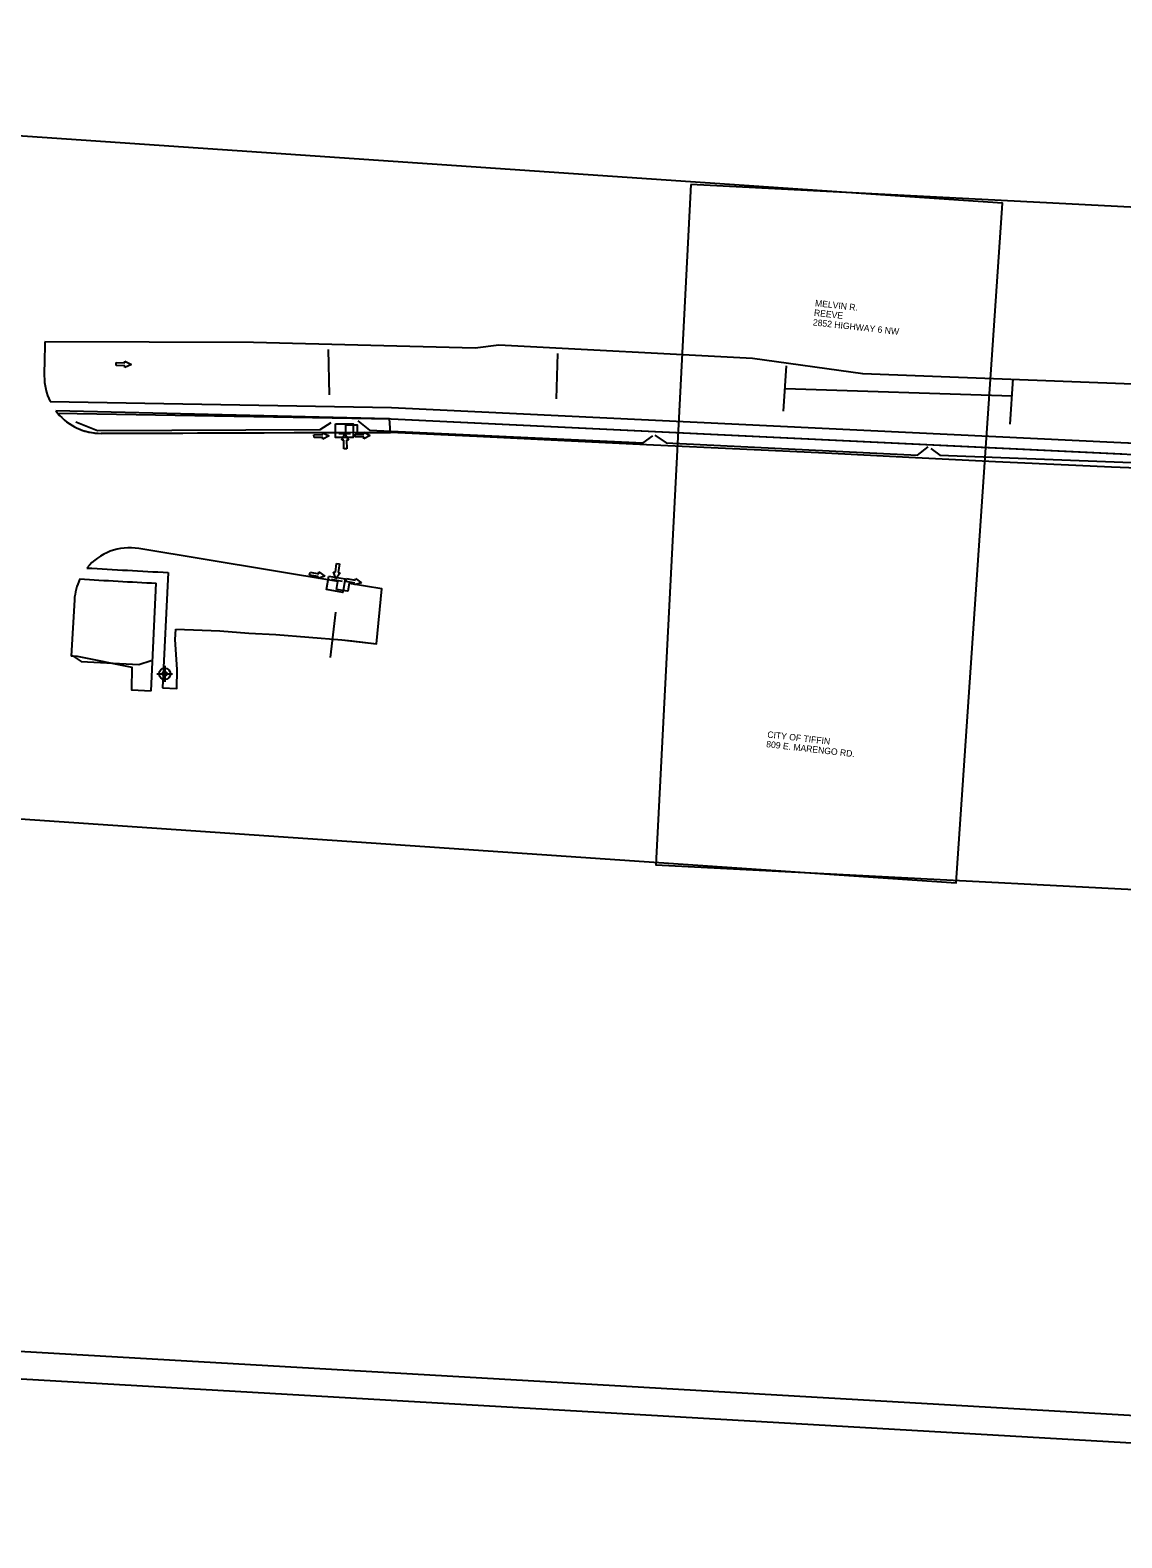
# Model space of a CAD drawing. Extents: x 20499990 to 20505779, y 7953198 to 7954399.
# Drawn here: x 20504549 to 20505029, y 7953198 to 7953862 of the extents above; entities that cross this region are included whole.
import ezdxf

# ---------------------------------------------------------------- set-up
doc = ezdxf.new("R2010")
doc.units = 0
for name, color, linetype in [('Building', 7, 'Continuous'), ('ClearGrub', 7, 'Continuous'), ('Draft_DNC', 7, 'Continuous'), ('dsnCellElements', 7, 'Continuous'), ('ErosionControl', 7, 'Continuous'), ('NamedBoundary', 7, 'Continuous'), ('Seeding', 7, 'Continuous'), ('Text', 7, 'Continuous')]:
    doc.layers.add(name, color=color, linetype=linetype)

msp = doc.modelspace()

# ---------------------------------------------------------------- linework, layer by layer
at = {"layer": 'Building'}
for p, q in [((20504555.07, 7953724.24), (20504554.94, 7953714.54)), ((20504554.97, 7953717.03), (20504554.87, 7953709.32)), ((20504557.42, 7953697.98), (20504707.7, 7953695.4)), ((20504560.72, 7953692.92), (20504707.68, 7953690.4)), ((20504707.7, 7953695.4), (20505028.88, 7953679.93)), ((20504707.68, 7953690.4), (20505029.34, 7953674.9)), ((20504707.3, 7953684.41), (20504579.95, 7953683.99)), ((20504684.17, 7953618.69), (20504596.48, 7953633.27)), ((20504609.4, 7953622.72), (20504606.93, 7953571.99)), ((20504601.86, 7953570.55), (20504604.16, 7953617.99)), ((20504683.59, 7953615.27), (20504684.17, 7953618.69)), ((20504568.15, 7953610.62), (20504566.72, 7953585.85)), ((20504612.77, 7953597.78), (20504632.15, 7953597.07))]:
    msp.add_line(p, q, dxfattribs=at)
for points in [[(20505264.52, 7953761.4), (20505255.15, 7953760.64), (20505223.48, 7953728.42), (20505118.14, 7953708.13), (20505064.87, 7953704.49), (20504915.31, 7953710.24), (20504866.73, 7953716.98), (20504755.09, 7953722.82), (20504744.66, 7953721.51), (20504646.98, 7953723.97), (20504555.07, 7953724.24)], [(20505061.3, 7953667.91), (20505051.67, 7953668.07), (20505024.81, 7953669.14), (20505009.01, 7953669.85), (20504973.68, 7953671.52), (20504935.49, 7953673.34), (20504898.88, 7953675.21), (20504861.14, 7953676.98), (20504823.16, 7953678.8), (20504783.91, 7953680.73), (20504745.3, 7953682.65), (20504710.5, 7953684.26), (20504707.21, 7953684.41)], [(20504632.15, 7953597.07), (20504644.99, 7953596.03), (20504656.88, 7953595.36), (20504685.89, 7953593.08), (20504690.26, 7953592.59), (20504701.1, 7953591.37), (20504703.49, 7953615.5), (20504689.1, 7953617.88), (20504688.52, 7953614.44), (20504686.25, 7953614.8), (20504683.59, 7953615.27)], [(20504606.93, 7953571.99), (20504613.28, 7953571.63), (20504613.37, 7953579.96), (20504612.45, 7953593.14), (20504612.77, 7953597.78)], [(20504566.73, 7953585.99), (20504569.42, 7953585.84), (20504593.38, 7953581.01), (20504593.28, 7953571), (20504601.86, 7953570.55)]]:
    msp.add_lwpolyline(points, dxfattribs=at)
for centre, radius, start, end in [((20504579.87, 7953708.99), 25, 179.23932, 206.12913), ((20504579.87, 7953708.99), 25, 219.99809, 270.18967), ((20505067.33, 7954478), 799, 267.24196, 281.40324), ((20504592.48, 7953609.23), 24.37, 80.56251, 140.65245), ((20504592.48, 7953609.23), 24.37, 154.15745, 176.71189), ((20504906, 7959377.59), 5767.5, 266.665603, 267.000099), ((20504906, 7959377.59), 5762.5, 266.69346, 267.049627)]:
    msp.add_arc(centre, radius, start, end, dxfattribs=at)
at = {"layer": 'ClearGrub'}
for p, q in [((20504607.89, 7953581.59), (20504607.89, 7953574.59)), ((20504604.39, 7953578.09), (20504611.39, 7953578.09))]:
    msp.add_line(p, q, dxfattribs=at)
for radius in [2.5, 1]:
    msp.add_circle((20504607.89, 7953578.09), radius, dxfattribs=at)
at = {"layer": 'Draft_DNC'}
for points in [[(20502378.98, 7953404.37), (20502465.54, 7954399.08), (20505611.36, 7954341.07), (20505615.95, 7953217.82)], [(20502519.96, 7953384.14), (20502606.52, 7954378.84), (20505752.34, 7954320.84), (20505756.93, 7953197.59)]]:
    msp.add_lwpolyline(points, close=True, dxfattribs=at)
at = {"layer": 'dsnCellElements'}
for p, q in [((20504586.53, 7953713.9), (20504586.57, 7953715.17)), ((20504590.35, 7953713.79), (20504586.53, 7953713.9)), ((20504586.57, 7953715.17), (20504590.39, 7953715.06)), ((20504593.23, 7953714.34), (20504590.33, 7953712.99)), ((20504590.33, 7953712.99), (20504590.35, 7953713.79)), ((20504590.39, 7953715.06), (20504590.41, 7953715.85)), ((20504590.41, 7953715.85), (20504593.23, 7953714.34)), ((20504673.63, 7953683.38), (20504677.45, 7953683.48)), ((20504673.67, 7953682.11), (20504673.63, 7953683.38)), ((20504677.48, 7953682.21), (20504673.67, 7953682.11)), ((20504677.43, 7953684.28), (20504680.33, 7953682.93)), ((20504677.45, 7953683.48), (20504677.43, 7953684.28)), ((20504677.5, 7953681.42), (20504677.48, 7953682.21)), ((20504680.33, 7953682.93), (20504677.5, 7953681.42)), ((20504685.92, 7953680.93), (20504687.26, 7953683.83)), ((20504686.71, 7953680.95), (20504685.92, 7953680.93)), ((20504686.82, 7953677.14), (20504686.71, 7953680.95)), ((20504687.26, 7953683.83), (20504688.78, 7953681.02)), ((20504688.78, 7953681.02), (20504687.98, 7953680.99)), ((20504687.98, 7953680.99), (20504688.09, 7953677.18)), ((20504691.74, 7953682.43), (20504691.75, 7953683.7)), ((20504695.55, 7953682.39), (20504691.74, 7953682.43)), ((20504691.75, 7953683.7), (20504695.56, 7953683.67)), ((20504698.42, 7953683), (20504695.54, 7953681.6)), ((20504695.54, 7953681.6), (20504695.55, 7953682.39)), ((20504695.56, 7953683.67), (20504695.57, 7953684.46)), ((20504695.57, 7953684.46), (20504698.42, 7953683)), ((20504688.09, 7953677.18), (20504686.82, 7953677.14)), ((20504683.04, 7953622.86), (20504683.55, 7953626.64)), ((20504683.55, 7953626.64), (20504684.81, 7953626.47)), ((20504684.81, 7953626.47), (20504684.3, 7953622.69)), ((20504671.72, 7953621.55), (20504671.93, 7953622.81)), ((20504675.48, 7953620.9), (20504671.72, 7953621.55)), ((20504671.93, 7953622.81), (20504675.69, 7953622.16)), ((20504678.41, 7953621.04), (20504675.34, 7953620.12)), ((20504675.34, 7953620.12), (20504675.48, 7953620.9)), ((20504675.69, 7953622.16), (20504675.83, 7953622.94)), ((20504675.83, 7953622.94), (20504678.41, 7953621.04)), ((20504683.28, 7953619.94), (20504682.25, 7953622.97)), ((20504682.25, 7953622.97), (20504683.04, 7953622.86)), ((20504685.09, 7953622.58), (20504683.28, 7953619.94)), ((20504684.3, 7953622.69), (20504685.09, 7953622.58)), ((20504687.79, 7953618.76), (20504688.01, 7953620.01)), ((20504688.01, 7953620.01), (20504691.77, 7953619.34)), ((20504691.77, 7953619.34), (20504691.91, 7953620.12)), ((20504691.91, 7953620.12), (20504694.48, 7953618.21)), ((20504691.55, 7953618.08), (20504687.79, 7953618.76)), ((20504694.48, 7953618.21), (20504691.41, 7953617.3)), ((20504691.41, 7953617.3), (20504691.55, 7953618.08))]:
    msp.add_line(p, q, dxfattribs=at)
at = {"layer": 'ErosionControl'}
for p, q in [((20504680.49, 7953700.9), (20504679.98, 7953720.9)), ((20504780.39, 7953699.2), (20504780.96, 7953719.19)), ((20504880.43, 7953693.79), (20504881.72, 7953713.75)), ((20504980.19, 7953688), (20504981.48, 7953707.95)), ((20504881.07, 7953703.77), (20504981.02, 7953700.58)), ((20504706.46, 7953690.42), (20504559.92, 7953693.92)), ((20504579.95, 7953683.99), (20504687.66, 7953684.34)), ((20504689.63, 7953683.77), (20504684.63, 7953683.79)), ((20504692.66, 7953684.36), (20504707.34, 7953684.41)), ((20504681.13, 7953619.76), (20504686.06, 7953618.93)), ((20504680.91, 7953585.31), (20504683.18, 7953605.18))]:
    msp.add_line(p, q, dxfattribs=at)
for points in [[(20504568.79, 7953689.13), (20504578.3, 7953685.24), (20504676.32, 7953685.69), (20504681.24, 7953688.79)], [(20504687.66, 7953684.34), (20504687.67, 7953687.79), (20504692.67, 7953687.77), (20504692.66, 7953684.36)], [(20504692.92, 7953689.57), (20504698.08, 7953685.42), (20504818.62, 7953679.78), (20504822.87, 7953682.91)], [(20504707.34, 7953684.41), (20504706.85, 7953690.4), (20504706.46, 7953690.42)], [(20504823.77, 7953683.14), (20504828.69, 7953679.78), (20504939.39, 7953674.41), (20504944.09, 7953677.99)], [(20504945.21, 7953677.32), (20504949.23, 7953674.41), (20505052.79, 7953670.38), (20505057.71, 7953673.07)], [(20504567.15, 7953586.16), (20504571.11, 7953583.57), (20504596.53, 7953582.2), (20504602, 7953583.95)]]:
    msp.add_lwpolyline(points, dxfattribs=at)
for points in [[(20504683.09, 7953688.24), (20504690.95, 7953688.24), (20504690.95, 7953682.17), (20504683.09, 7953682.17)], [(20504680.11, 7953621.11), (20504687.33, 7953619.9), (20504686.33, 7953613.97), (20504679.11, 7953615.18)]]:
    msp.add_lwpolyline(points, close=True, dxfattribs=at)
msp.add_arc((20504579.87, 7953708.99), 25, 217.05957, 270.18967, dxfattribs=at)
at = {"layer": 'NamedBoundary'}
for points in [[(20504038.63, 7953849.54), (20504018.15, 7953550.24), (20504956.36, 7953486.07), (20504976.83, 7953785.37)], [(20504839.57, 7953793.6), (20504824.13, 7953494), (20505763.38, 7953445.57), (20505778.83, 7953745.18)]]:
    msp.add_lwpolyline(points, close=True, dxfattribs=at)
at = {"layer": 'Seeding'}
for p, q in [((20504555.07, 7953724.24), (20504554.94, 7953714.54)), ((20504554.97, 7953717.03), (20504554.87, 7953709.32)), ((20504557.42, 7953697.98), (20504707.7, 7953695.4)), ((20504560.72, 7953692.92), (20504707.68, 7953690.4)), ((20504707.7, 7953695.4), (20505028.88, 7953679.93)), ((20504707.68, 7953690.4), (20505028.64, 7953674.94)), ((20504707.3, 7953684.41), (20504579.95, 7953683.99)), ((20504684.17, 7953618.69), (20504596.48, 7953633.27)), ((20504609.4, 7953622.72), (20504606.93, 7953571.99)), ((20504601.86, 7953570.55), (20504604.16, 7953617.99)), ((20504683.61, 7953615.28), (20504684.17, 7953618.69)), ((20504568.15, 7953610.62), (20504566.72, 7953585.85)), ((20504612.77, 7953597.78), (20504632.15, 7953597.07))]:
    msp.add_line(p, q, dxfattribs=at)
for points in [[(20505264.52, 7953761.4), (20505255.15, 7953760.64), (20505223.48, 7953728.42), (20505118.14, 7953708.13), (20505064.87, 7953704.49), (20504915.31, 7953710.24), (20504866.73, 7953716.98), (20504755.09, 7953722.82), (20504744.66, 7953721.51), (20504646.98, 7953723.97), (20504555.07, 7953724.24)], [(20505061.3, 7953667.91), (20505051.67, 7953668.07), (20505024.81, 7953669.14), (20505009.01, 7953669.85), (20504973.68, 7953671.52), (20504935.49, 7953673.34), (20504898.88, 7953675.21), (20504861.14, 7953676.98), (20504823.16, 7953678.8), (20504783.91, 7953680.73), (20504745.3, 7953682.65), (20504710.5, 7953684.26), (20504707.21, 7953684.41)], [(20504632.15, 7953597.07), (20504644.99, 7953596.03), (20504656.88, 7953595.36), (20504685.89, 7953593.08), (20504701.1, 7953591.37), (20504703.49, 7953615.5), (20504689.1, 7953617.88), (20504688.52, 7953614.44), (20504686.25, 7953614.84), (20504683.61, 7953615.28)], [(20504606.93, 7953571.99), (20504613.28, 7953571.63), (20504613.37, 7953579.96), (20504612.45, 7953593.14), (20504612.77, 7953597.78)], [(20504566.73, 7953585.99), (20504569.42, 7953585.84), (20504593.38, 7953581.01), (20504593.28, 7953571), (20504601.86, 7953570.55)]]:
    msp.add_lwpolyline(points, dxfattribs=at)
for centre, radius, start, end in [((20504579.87, 7953708.99), 25, 179.23932, 206.12913), ((20504579.87, 7953708.99), 25, 219.99809, 270.18967), ((20505067.33, 7954478), 799, 267.24196, 282.60964), ((20505067.14, 7954474.15), 800.15, 267.24197, 281.0968), ((20504592.48, 7953609.23), 24.37, 80.56251, 140.65245), ((20504592.48, 7953609.23), 24.37, 154.15745, 176.71189), ((20504906, 7959377.59), 5767.5, 266.665603, 267.000099), ((20504906, 7959377.59), 5762.5, 266.69346, 267.049627)]:
    msp.add_arc(centre, radius, start, end, dxfattribs=at)

# ---------------------------------------------------------------- texts
at = {"layer": 'Text'}
for s, height, rotation, p in [('MELVIN R. ', 2.835, 353.65909, (20504894.12, 7953740.01)), ('2852 HIGHWAY 6 NW', 2.8346, 353.65909, (20504893.18, 7953731.56)), ('REEVE', 2.835, 353.65909, (20504893.65, 7953735.79)), ('809 E. MARENGO RD.', 2.8346, 353.49015, (20504872.64, 7953545.82)), ('CITY OF TIFFIN', 2.8346, 353.49015, (20504873.12, 7953550.04))]:
    msp.add_text(s, height=height, rotation=rotation, dxfattribs=at).set_placement(p)

doc.saveas('drawing.dxf')
